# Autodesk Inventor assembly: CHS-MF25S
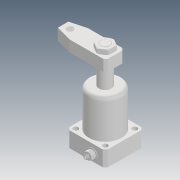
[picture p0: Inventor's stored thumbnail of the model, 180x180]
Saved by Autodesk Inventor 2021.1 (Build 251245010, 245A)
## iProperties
Created: 2019-04
Part Number: CHS-MF25S
Description: STEP AP203
Document SubType Name: Assembly
Designer: user
Title: chs-mf25s_asm.STEP
Revision Number: ÈÎºÎ
Sending System: SolidWorks 2017
Preprocessor: SwSTEP 2.0
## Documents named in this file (9)
- D:\Vault_2016\Projekty\Clamptek\Hydraulic\CHS\CHS-25\Inventor\CHS-MF25S\CHS-MF25S.iam
- D:\Vault_2016\Projekty\Clamptek\Hydraulic\CHS\CHS-25\Inventor\CHS-MF25S\CHS-MF25BT.ipt
- D:\Vault_2016\Projekty\Clamptek\Hydraulic\CHS\CHS-25\Inventor\CHS-MF25S\CHS-25S-02_4.ipt
- D:\Vault_2016\Projekty\Clamptek\Hydraulic\CHS\CHS-25\Inventor\CHS-MF25S\CHS-25S-01_4.ipt
- D:\Vault_2016\Projekty\Clamptek\Hydraulic\CHS\CHS-25\Inventor\CHS-MF25S\M14_4.ipt
- D:\Vault_2016\Projekty\Clamptek\Hydraulic\CHS\CHS-25\Inventor\CHS-MF25S\CHS-TXF-01_1.ipt
- D:\Vault_2016\Projekty\Clamptek\Hydraulic\CHS\CHS-25\Inventor\CHS-MF25S\CHS-MF25-TXF-03_1.ipt
- D:\Vault_2016\Projekty\Clamptek\Hydraulic\CHS\CHS-25\Inventor\CHS-MF25S\CHS-MF25-TXF-02_1.ipt
- D:\Vault_2016\Projekty\Clamptek\Hydraulic\CHS\CHS-25\Inventor\CHS-MF25S\M6_1.ipt
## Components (8 placed, 8 different names)
1. CHS-MF25BT_1
2. CHS-25S-02_4_2
3. CHS-25S-01_4_3
4. M14_4_4
5. CHS-TXF-01_1_5
6. CHS-MF25-TXF-03_1_6
7. CHS-MF25-TXF-02_1_7
8. M6_1_8
